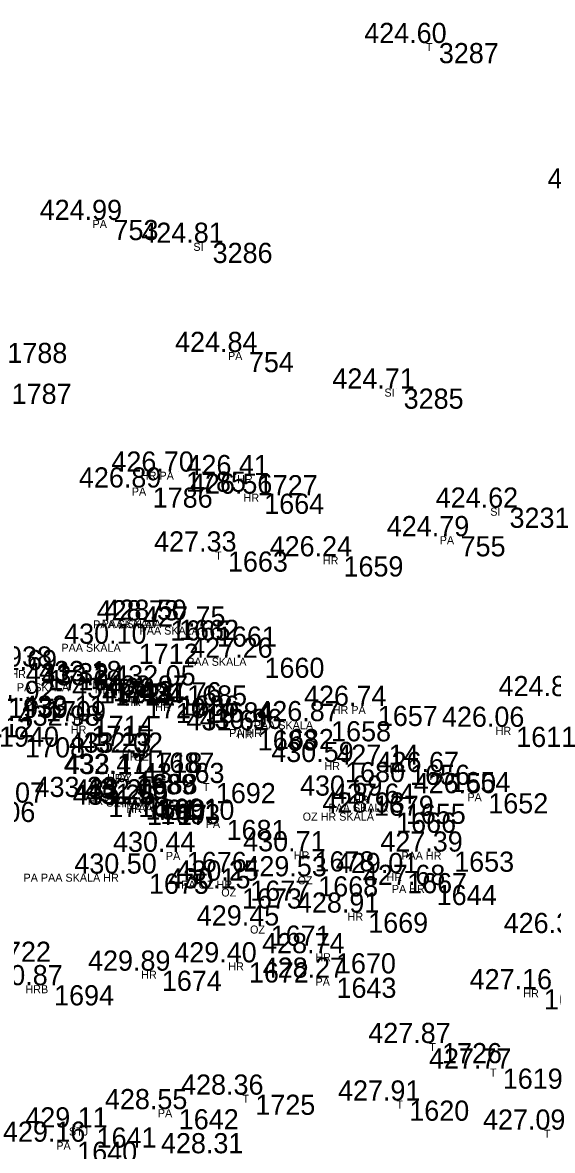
# Model space of a CAD drawing. Extents: x -639390 to -639075, y -1138747 to -1138358.
# Drawn here: x -639262.82 to -639243.09, y -1138562.26 to -1138520.32 of the extents above; entities that cross this region are included whole.
import ezdxf

# ---------------------------------------------------------------- set-up
doc = ezdxf.new("R2010")
doc.units = 0
for name, color, linetype in [('Vrstva 11', 7, 'Continuous'), ('Vrstva 12', 7, 'Continuous'), ('Vrstva 13', 7, 'Continuous'), ('Vrstva 57', 7, 'Continuous')]:
    doc.layers.add(name, color=color, linetype=linetype)

msp = doc.modelspace()

# ---------------------------------------------------------------- linework, layer by layer
at = {"layer": 'Vrstva 11'}
for p, q in [((-639247.6, -1138521.08), (-639247.6, -1138521.08)), ((-639259.71, -1138527.66), (-639259.71, -1138527.66)), ((-639256.02, -1138528.51), (-639256.02, -1138528.51)), ((-639254.67, -1138532.57), (-639254.67, -1138532.57)), ((-639248.91, -1138533.93), (-639248.91, -1138533.93)), ((-639257.01, -1138537.02), (-639257.01, -1138537.02)), ((-639254.34, -1138537.15), (-639254.34, -1138537.15)), ((-639258.25, -1138537.61), (-639258.25, -1138537.61)), ((-639254.1, -1138537.84), (-639254.1, -1138537.84)), ((-639244.97, -1138538.36), (-639244.97, -1138538.36)), ((-639246.79, -1138539.42), (-639246.79, -1138539.42)), ((-639255.45, -1138539.99), (-639255.45, -1138539.99)), ((-639251.15, -1138540.17), (-639251.15, -1138540.17)), ((-639257.27, -1138542.53), (-639257.27, -1138542.53)), ((-639257.59, -1138542.55), (-639257.59, -1138542.55)), ((-639255.86, -1138542.78), (-639255.86, -1138542.78)), ((-639258.77, -1138543.42), (-639258.77, -1138543.42)), ((-639254.09, -1138543.94), (-639254.09, -1138543.94)), ((-639262.13, -1138544.4), (-639262.13, -1138544.4)), ((-639260.23, -1138544.89), (-639260.23, -1138544.89)), ((-639259.73, -1138544.81), (-639259.73, -1138544.81)), ((-639259.64, -1138544.97), (-639259.64, -1138544.97)), ((-639256.97, -1138544.97), (-639256.97, -1138544.97)), ((-639258.5, -1138545.44), (-639258.5, -1138545.44)), ((-639257.26, -1138545.35), (-639257.26, -1138545.35)), ((-639262.22, -1138545.55), (-639262.22, -1138545.55)), ((-639257.39, -1138545.62), (-639257.39, -1138545.62)), ((-639255.99, -1138545.6), (-639255.99, -1138545.6)), ((-639249.87, -1138545.73), (-639249.87, -1138545.73)), ((-639260.45, -1138546.1), (-639260.45, -1138546.1)), ((-639251.61, -1138546.3), (-639251.61, -1138546.3)), ((-639260.53, -1138546.47), (-639260.53, -1138546.47)), ((-639254.34, -1138546.64), (-639254.34, -1138546.64)), ((-639253.74, -1138546.59), (-639253.74, -1138546.59)), ((-639244.72, -1138546.51), (-639244.72, -1138546.51)), ((-639258.63, -1138547.47), (-639258.63, -1138547.47)), ((-639258.19, -1138547.47), (-639258.19, -1138547.47)), ((-639251.09, -1138547.82), (-639251.09, -1138547.82)), ((-639248.67, -1138547.92), (-639248.67, -1138547.92)), ((-639258.87, -1138548.27), (-639258.87, -1138548.27)), ((-639258.81, -1138548.26), (-639258.81, -1138548.26)), ((-639247.17, -1138548.19), (-639247.17, -1138548.19)), ((-639255.9, -1138548.6), (-639255.9, -1138548.6)), ((-639259.9, -1138549.12), (-639259.9, -1138549.12)), ((-639258.52, -1138549.21), (-639258.52, -1138549.21)), ((-639258.02, -1138549.18), (-639258.02, -1138549.18)), ((-639250.02, -1138549.07), (-639250.02, -1138549.07)), ((-639245.76, -1138548.98), (-639245.76, -1138548.98)), ((-639258.46, -1138549.41), (-639258.46, -1138549.41)), ((-639257.97, -1138549.38), (-639257.97, -1138549.38)), ((-639248.83, -1138549.37), (-639248.83, -1138549.37)), ((-639255.5, -1138549.97), (-639255.5, -1138549.97)), ((-639249.19, -1138549.7), (-639249.19, -1138549.7)), ((-639256.98, -1138551.16), (-639256.98, -1138551.16)), ((-639252.23, -1138551.14), (-639252.23, -1138551.14)), ((-639247.03, -1138551.15), (-639247.03, -1138551.15)), ((-639258.39, -1138551.97), (-639258.39, -1138551.97)), ((-639252.09, -1138552.07), (-639252.09, -1138552.07)), ((-639248.78, -1138551.95), (-639248.78, -1138551.95)), ((-639254.93, -1138552.52), (-639254.93, -1138552.52)), ((-639254.62, -1138552.23), (-639254.62, -1138552.23)), ((-639247.68, -1138552.39), (-639247.68, -1138552.39)), ((-639250.23, -1138553.42), (-639250.23, -1138553.42)), ((-639253.86, -1138553.9), (-639253.86, -1138553.9)), ((-639251.43, -1138554.93), (-639251.43, -1138554.93)), ((-639254.67, -1138555.27), (-639254.67, -1138555.27)), ((-639257.91, -1138555.58), (-639257.91, -1138555.58)), ((-639251.41, -1138555.84), (-639251.41, -1138555.84)), ((-639261.92, -1138556.12), (-639261.92, -1138556.12)), ((-639243.69, -1138556.27), (-639243.69, -1138556.27)), ((-639247.48, -1138558.27), (-639247.48, -1138558.27)), ((-639245.22, -1138559.22), (-639245.22, -1138559.22)), ((-639254.43, -1138560.19), (-639254.43, -1138560.19)), ((-639248.7, -1138560.41), (-639248.7, -1138560.41)), ((-639257.28, -1138560.73), (-639257.28, -1138560.73)), ((-639260.34, -1138561.41), (-639260.34, -1138561.41)), ((-639243.21, -1138561.49), (-639243.21, -1138561.49)), ((-639261.06, -1138561.94), (-639261.06, -1138561.94))]:
    msp.add_line(p, q, dxfattribs=at)

# ---------------------------------------------------------------- texts
at = {"layer": 'Vrstva 12'}
for s, p in [('424.60 ', (-639250.099, -1138521.08)), ('424.51 ', (-639243.275, -1138526.49)), ('424.99 ', (-639262.179, -1138527.66)), ('424.81 ', (-639258.395, -1138528.51)), ('424.84 ', (-639257.139, -1138532.57)), ('424.71 ', (-639251.285, -1138533.93)), ('426.70 ', (-639259.509, -1138537.02)), ('426.41 ', (-639256.715, -1138537.15)), ('426.89 ', (-639260.719, -1138537.61)), ('426.56 ', (-639256.586, -1138537.84)), ('424.62 ', (-639247.439, -1138538.36)), ('424.79 ', (-639249.259, -1138539.42)), ('427.33 ', (-639257.919, -1138539.99)), ('426.24 ', (-639253.619, -1138540.17)), ('428.73 ', (-639260.059, -1138542.55)), ('428.50 ', (-639259.769, -1138542.53)), ('427.75 ', (-639258.33, -1138542.78)), ('430.10 ', (-639261.269, -1138543.42)), ('427.26 ', (-639256.576, -1138543.94)), ('431.69 ', (-639264.599, -1138544.4)), ('431.32 ', (-639262.699, -1138544.89)), ('433.18 ', (-639262.199, -1138544.81)), ('433.24 ', (-639262.109, -1138544.97)), ('432.05 ', (-639259.44, -1138544.97)), ('432.97 ', (-639259.729, -1138545.35)), ('424.80 ', (-639245.099, -1138545.37)), ('431.92 ', (-639264.689, -1138545.55)), ('433.22 ', (-639260.969, -1138545.44)), ('433.24 ', (-639259.859, -1138545.62)), ('431.76 ', (-639258.476, -1138545.6)), ('426.74 ', (-639252.339, -1138545.73)), ('433.11 ', (-639262.825, -1138546.1)), ('432.98 ', (-639262.999, -1138546.47)), ('431.61 ', (-639256.715, -1138546.64)), ('430.96 ', (-639256.226, -1138546.59)), ('426.87 ', (-639254.079, -1138546.3)), ('426.06 ', (-639247.206, -1138546.51)), ('432.12 ', (-639265.469, -1138546.9)), ('433.23 ', (-639261.099, -1138547.47)), ('432.02 ', (-639260.659, -1138547.47)), ('430.59 ', (-639253.559, -1138547.82)), ('427.14 ', (-639251.139, -1138547.92)), ('432.47 ', (-639261.279, -1138548.26)), ('433.11 ', (-639261.245, -1138548.27)), ('426.67 ', (-639249.639, -1138548.19)), ('431.63 ', (-639258.369, -1138548.6)), ('433.38 ', (-639262.369, -1138549.12)), ('432.05 ', (-639260.49, -1138549.18)), ('430.69 ', (-639252.489, -1138549.07)), ('426.50 ', (-639248.259, -1138548.98)), ('433.26 ', (-639260.946, -1138549.41)), ('433.21 ', (-639260.895, -1138549.21)), ('431.50 ', (-639260.469, -1138549.38)), ('427.64 ', (-639251.299, -1138549.37)), ('431.10 ', (-639257.999, -1138549.97)), ('428.93 ', (-639251.659, -1138549.7)), ('430.44 ', (-639259.449, -1138551.16)), ('430.71 ', (-639254.605, -1138551.14)), ('427.39 ', (-639249.499, -1138551.15)), ('430.50 ', (-639260.889, -1138551.97)), ('429.53 ', (-639254.559, -1138552.07)), ('429.01 ', (-639251.155, -1138551.95)), ('430.15 ', (-639257.4, -1138552.52)), ('430.25 ', (-639257.09, -1138552.23)), ('427.68 ', (-639250.149, -1138552.39)), ('428.91 ', (-639252.605, -1138553.42)), ('429.45 ', (-639256.33, -1138553.9)), ('426.39 ', (-639244.909, -1138554.18)), ('428.74 ', (-639253.899, -1138554.93)), ('429.40 ', (-639257.169, -1138555.27)), ('429.89 ', (-639260.379, -1138555.58)), ('428.27 ', (-639253.879, -1138555.84)), ('430.87 ', (-639264.389, -1138556.12)), ('427.16 ', (-639246.176, -1138556.27)), ('427.87 ', (-639249.949, -1138558.27)), ('427.77 ', (-639247.689, -1138559.22)), ('428.36 ', (-639256.916, -1138560.19)), ('427.91 ', (-639251.075, -1138560.41)), ('428.55 ', (-639259.75, -1138560.73)), ('429.11 ', (-639262.715, -1138561.41)), ('427.09 ', (-639245.679, -1138561.49)), ('429.16 ', (-639263.546, -1138561.94)), ('428.31 ', (-639257.665, -1138562.37))]:
    msp.add_text(s, height=0.75, dxfattribs=at).set_placement(p)
at = {"layer": 'Vrstva 13'}
for s, p in [(' 3287', (-639247.6, -1138521.83)), (' 753', (-639259.71, -1138528.41)), (' 3286', (-639256.02, -1138529.26)), (' 1788', (-639263.66, -1138532.98)), (' 754', (-639254.67, -1138533.32)), (' 1787', (-639263.5, -1138534.5)), (' 3285', (-639248.91, -1138534.68)), (' 1785', (-639257.01, -1138537.77)), (' 1727', (-639254.34, -1138537.9)), (' 1786', (-639258.25, -1138538.36)), (' 1664', (-639254.1, -1138538.59)), (' 3231', (-639244.97, -1138539.11)), (' 755', (-639246.79, -1138540.17)), (' 1663', (-639255.45, -1138540.74)), (' 1659', (-639251.15, -1138540.92)), (' 1665', (-639257.59, -1138543.3)), (' 1662', (-639257.27, -1138543.28)), (' 1661', (-639255.86, -1138543.53)), (' 1938', (-639264.23, -1138544.27)), (' 1712', (-639258.77, -1138544.17)), (' 1660', (-639254.09, -1138544.69)), (' 1710', (-639262.13, -1138545.15)), (' 1711', (-639260.23, -1138545.64)), (' 1713', (-639259.73, -1138545.56)), (' 1721', (-639259.64, -1138545.72)), (' 1685', (-639256.97, -1138545.72)), (' 1939', (-639263.63, -1138546.18)), (' 1720', (-639258.5, -1138546.19)), (' 1686', (-639257.26, -1138546.1)), (' 1709', (-639262.22, -1138546.3)), (' 1719', (-639257.39, -1138546.37)), (' 1684', (-639255.99, -1138546.35)), (' 1657', (-639249.87, -1138546.48)), (' 1714', (-639260.45, -1138546.85)), (' 1658', (-639251.61, -1138547.05)), (' 1940', (-639263.97, -1138547.25)), (' 1715', (-639260.53, -1138547.22)), (' 1683', (-639254.34, -1138547.39)), (' 1682', (-639253.74, -1138547.34)), (' 1611', (-639244.72, -1138547.26)), (' 1708', (-639263, -1138547.65)), (' 1718', (-639258.63, -1138548.22)), (' 1687', (-639258.19, -1138548.22)), (' 1680', (-639251.09, -1138548.57)), (' 1656', (-639248.67, -1138548.67)), (' 1689', (-639258.87, -1138549.02)), (' 1688', (-639258.81, -1138549.01)), (' 1654', (-639247.17, -1138548.94)), (' 1707', (-639264.49, -1138549.33)), (' 1692', (-639255.9, -1138549.35)), (' 1716', (-639259.9, -1138549.87)), (' 1690', (-639258.52, -1138549.96)), (' 1691', (-639258.02, -1138549.93)), (' 1679', (-639250.02, -1138549.82)), (' 1652', (-639245.76, -1138549.73)), (' 1706', (-639264.85, -1138550.05)), (' 1717', (-639258.46, -1138550.16)), (' 1693', (-639257.97, -1138550.13)), (' 1655', (-639248.83, -1138550.12)), (' 1681', (-639255.5, -1138550.72)), (' 1666', (-639249.19, -1138550.45)), (' 1676', (-639256.98, -1138551.91)), (' 1678', (-639252.23, -1138551.89)), (' 1653', (-639247.03, -1138551.9)), (' 1675', (-639258.39, -1138552.72)), (' 1668', (-639252.09, -1138552.82)), (' 1667', (-639248.78, -1138552.7)), (' 1673', (-639254.93, -1138553.27)), (' 1677', (-639254.62, -1138552.98)), (' 1644', (-639247.68, -1138553.14)), (' 1669', (-639250.23, -1138554.17)), (' 1671', (-639253.86, -1138554.65)), (' 1722', (-639264.27, -1138555.25)), (' 1670', (-639251.43, -1138555.68)), (' 1672', (-639254.67, -1138556.02)), (' 1674', (-639257.91, -1138556.33)), (' 1643', (-639251.41, -1138556.59)), (' 1694', (-639261.92, -1138556.87)), (' 1645', (-639243.69, -1138557.02)), (' 1726', (-639247.48, -1138559.02)), (' 1619', (-639245.22, -1138559.97)), (' 1725', (-639254.43, -1138560.94)), (' 1620', (-639248.7, -1138561.16)), (' 1642', (-639257.28, -1138561.48)), (' 1641', (-639260.34, -1138562.16)), (' 1640', (-639261.06, -1138562.69))]:
    msp.add_text(s, height=0.75, dxfattribs=at).set_placement(p)
at = {"layer": 'Vrstva 57'}
for s, p in [('T', (-639247.8, -1138521.38)), ('PA', (-639260.21, -1138527.96)), ('SI', (-639256.458, -1138528.81)), ('PA', (-639255.17, -1138532.87)), ('SI', (-639249.348, -1138534.23)), ('HR PA', (-639258.41, -1138537.32)), ('HR', (-639254.829, -1138537.45)), ('PA', (-639258.75, -1138537.91)), ('HR', (-639254.589, -1138538.14)), ('SI', (-639245.408, -1138538.66)), ('PA', (-639247.29, -1138539.72)), ('T', (-639255.65, -1138540.29)), ('HR', (-639251.639, -1138540.47)), ('PAA SKALA', (-639260.19, -1138542.85)), ('PAA SKALA', (-639259.87, -1138542.83)), ('PAA SKALA', (-639258.46, -1138543.08)), ('PAA SKALA', (-639261.37, -1138543.72)), ('PAA SKALA', (-639256.69, -1138544.24)), ('PA SKALA HR', (-639265.319, -1138544.7)), ('HR PAA PA SKALA', (-639264.63, -1138545.19)), ('HR', (-639260.219, -1138545.11)), ('HR', (-639260.129, -1138545.27)), ('HR OZ HRA', (-639259.57, -1138545.27)), ('HR', (-639258.989, -1138545.74)), ('HRA', (-639258.06, -1138545.65)), ('PA', (-639262.72, -1138545.85)), ('HR', (-639257.879, -1138545.92)), ('HR', (-639256.479, -1138545.9)), ('HR PA', (-639251.27, -1138546.03)), ('HR', (-639260.939, -1138546.4)), ('PAA SKALA', (-639254.21, -1138546.6)), ('HR', (-639261.019, -1138546.77)), ('PA HR', (-639255.129, -1138546.89)), ('HR', (-639254.829, -1138546.94)), ('HR', (-639245.209, -1138546.81)), ('HR', (-639259.119, -1138547.77)), ('OZ', (-639258.679, -1138547.77)), ('HR', (-639251.579, -1138548.12)), ('HR', (-639249.159, -1138548.22)), ('HRA', (-639259.67, -1138548.57)), ('OZ', (-639259.299, -1138548.56)), ('PA', (-639247.67, -1138548.49)), ('T', (-639256.1, -1138548.9)), ('HR', (-639260.389, -1138549.42)), ('OZ PAA', (-639259.72, -1138549.48)), ('HRA', (-639259.32, -1138549.51)), ('HR', (-639250.509, -1138549.37)), ('PA', (-639246.26, -1138549.28)), ('HR', (-639258.949, -1138549.71)), ('PAA', (-639258.77, -1138549.68)), ('PAA SKALA', (-639251.43, -1138549.67)), ('PA', (-639256, -1138550.27)), ('OZ HR SKALA', (-639252.39, -1138550)), ('PA', (-639257.48, -1138551.46)), ('HR', (-639252.719, -1138551.44)), ('PAA HR', (-639248.719, -1138551.45)), ('PA PAA SKALA HR', (-639262.779, -1138552.27)), ('OZ', (-639252.579, -1138552.37)), ('HR', (-639249.269, -1138552.25)), ('PA OZ HR', (-639256.909, -1138552.53)), ('OZ', (-639255.419, -1138552.82)), ('PA HR', (-639249.069, -1138552.69)), ('HR', (-639250.719, -1138553.72)), ('OZ', (-639254.349, -1138554.2)), ('HR', (-639251.919, -1138555.23)), ('HR', (-639255.159, -1138555.57)), ('HR', (-639258.399, -1138555.88)), ('PA', (-639251.91, -1138556.14)), ('HRB', (-639262.709, -1138556.42)), ('HR', (-639244.179, -1138556.57)), ('T', (-639247.68, -1138558.57)), ('T', (-639245.42, -1138559.52)), ('T', (-639254.63, -1138560.49)), ('T', (-639248.9, -1138560.71)), ('PA', (-639257.78, -1138561.03)), ('STJ', (-639261.09, -1138561.71)), ('T', (-639243.41, -1138561.79)), ('PA', (-639261.56, -1138562.24))]:
    msp.add_text(s, height=0.3, dxfattribs=at).set_placement(p)

doc.saveas('drawing.dxf')
